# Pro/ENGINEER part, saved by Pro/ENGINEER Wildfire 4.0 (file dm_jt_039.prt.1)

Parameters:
  METRIC = "NO"

Other parameters: PITCH, DRILL_POINT_ANGLE, DRILL_DEPTH, DRILL_DIAMETER, THREAD_DIAMETER, THREADS_PER_INCH, THREAD_DEPTH, THREAD_LENGTH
